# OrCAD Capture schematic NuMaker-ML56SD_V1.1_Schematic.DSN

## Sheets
1 Nu-Link2-Me: size A3; title: Nu-Link2-Me; rev: 1.0; company: CMHuang; note: Nu-Link2-Me
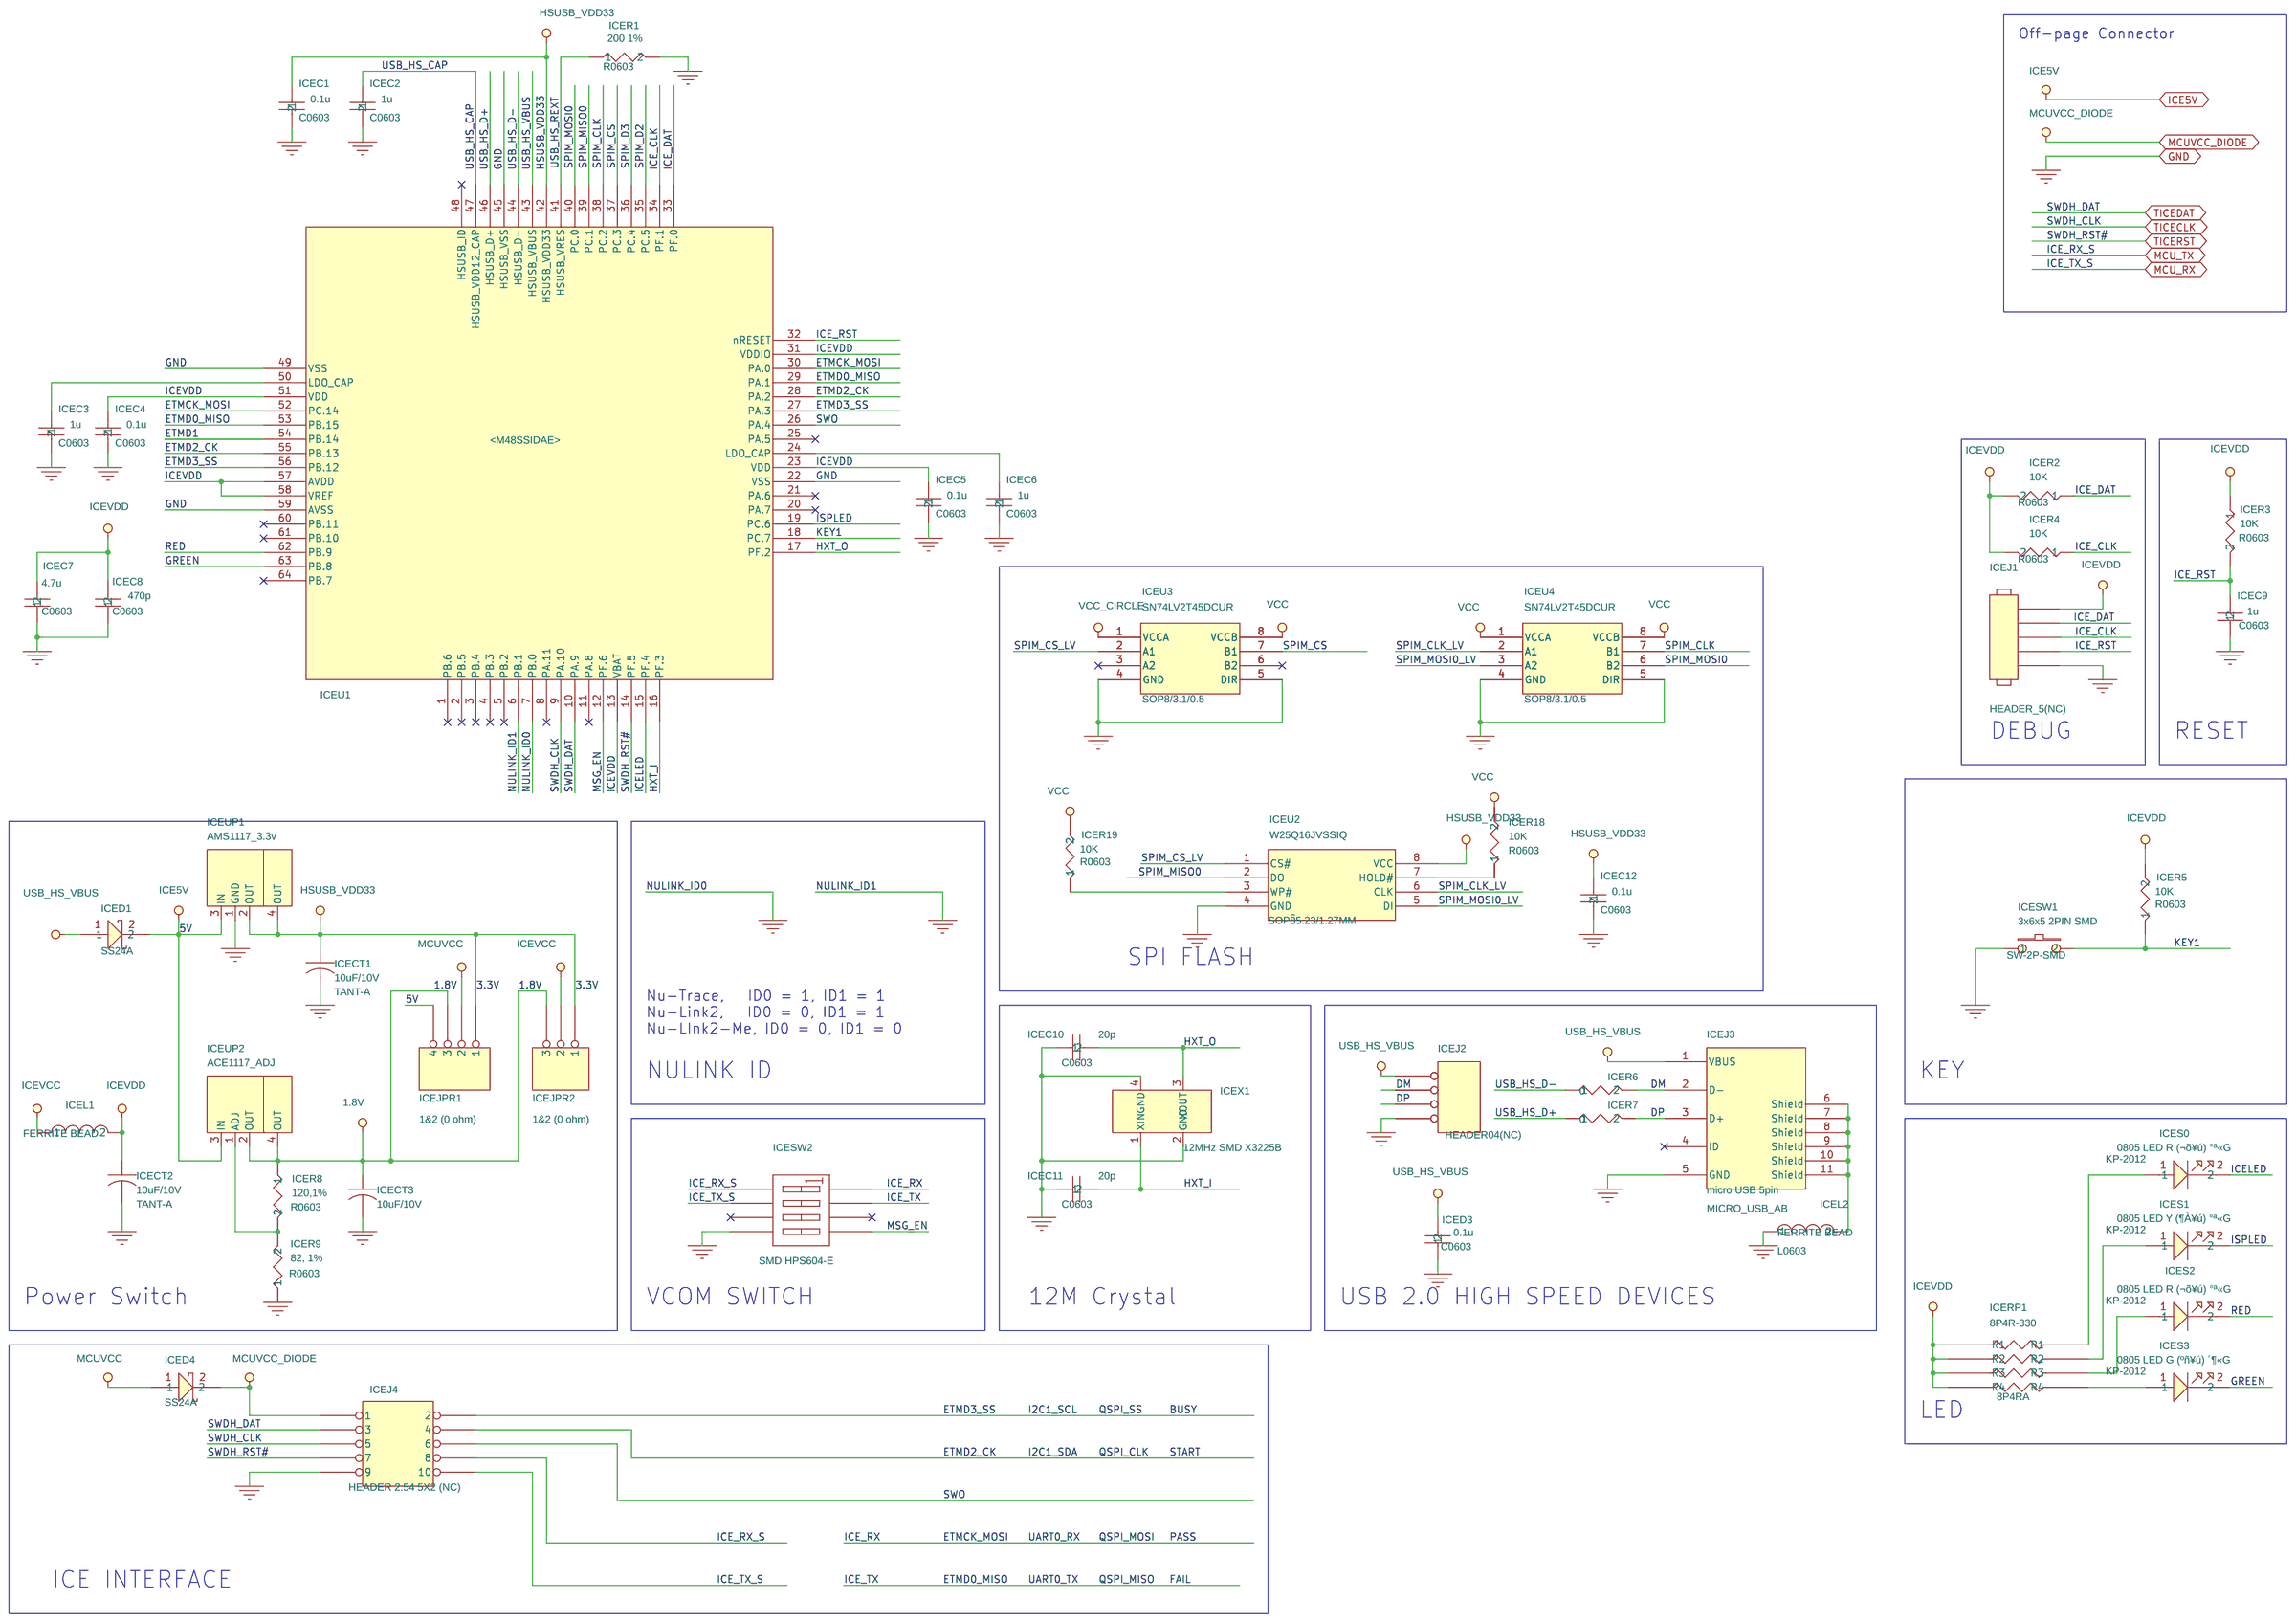
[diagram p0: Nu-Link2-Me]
2 ML56SD1AE: size Custom; title: ML56SD1AE; rev: v1.1; note: NuMaker-ML56SD
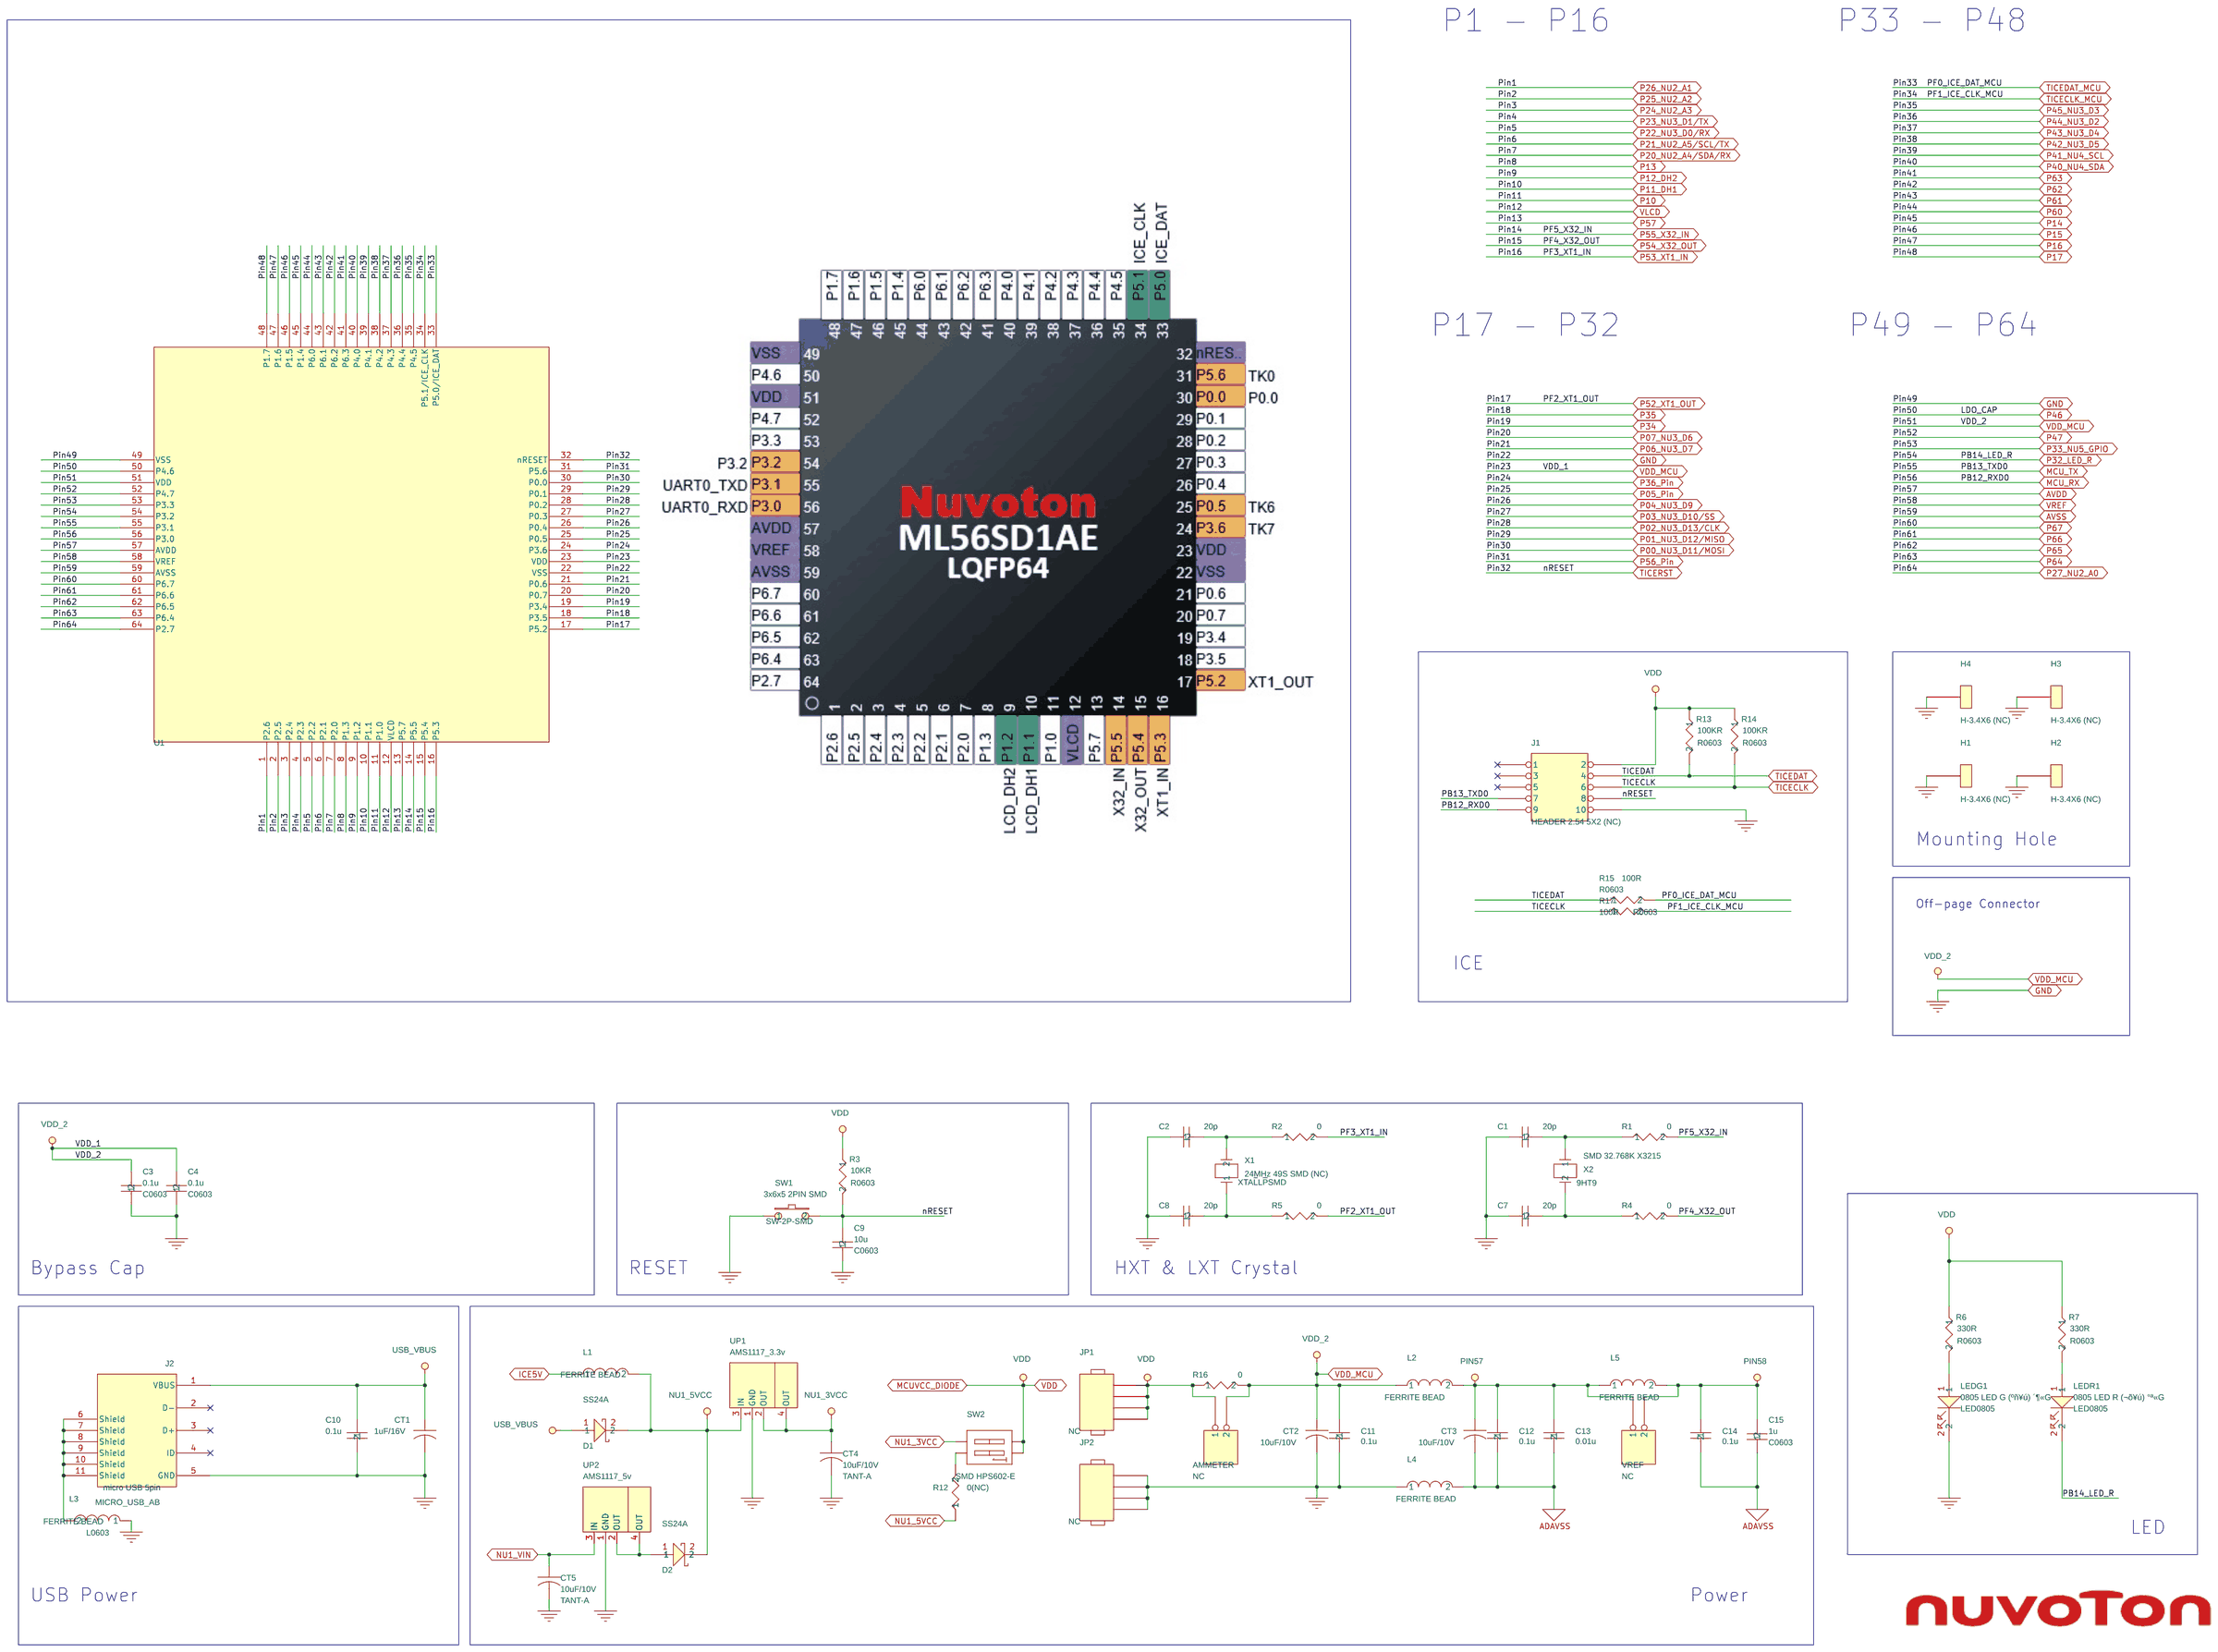
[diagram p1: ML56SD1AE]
3 Ext. Connector: size Custom; title: Ext. Connector; rev: v1.1; note: NuMaker-ML56SD
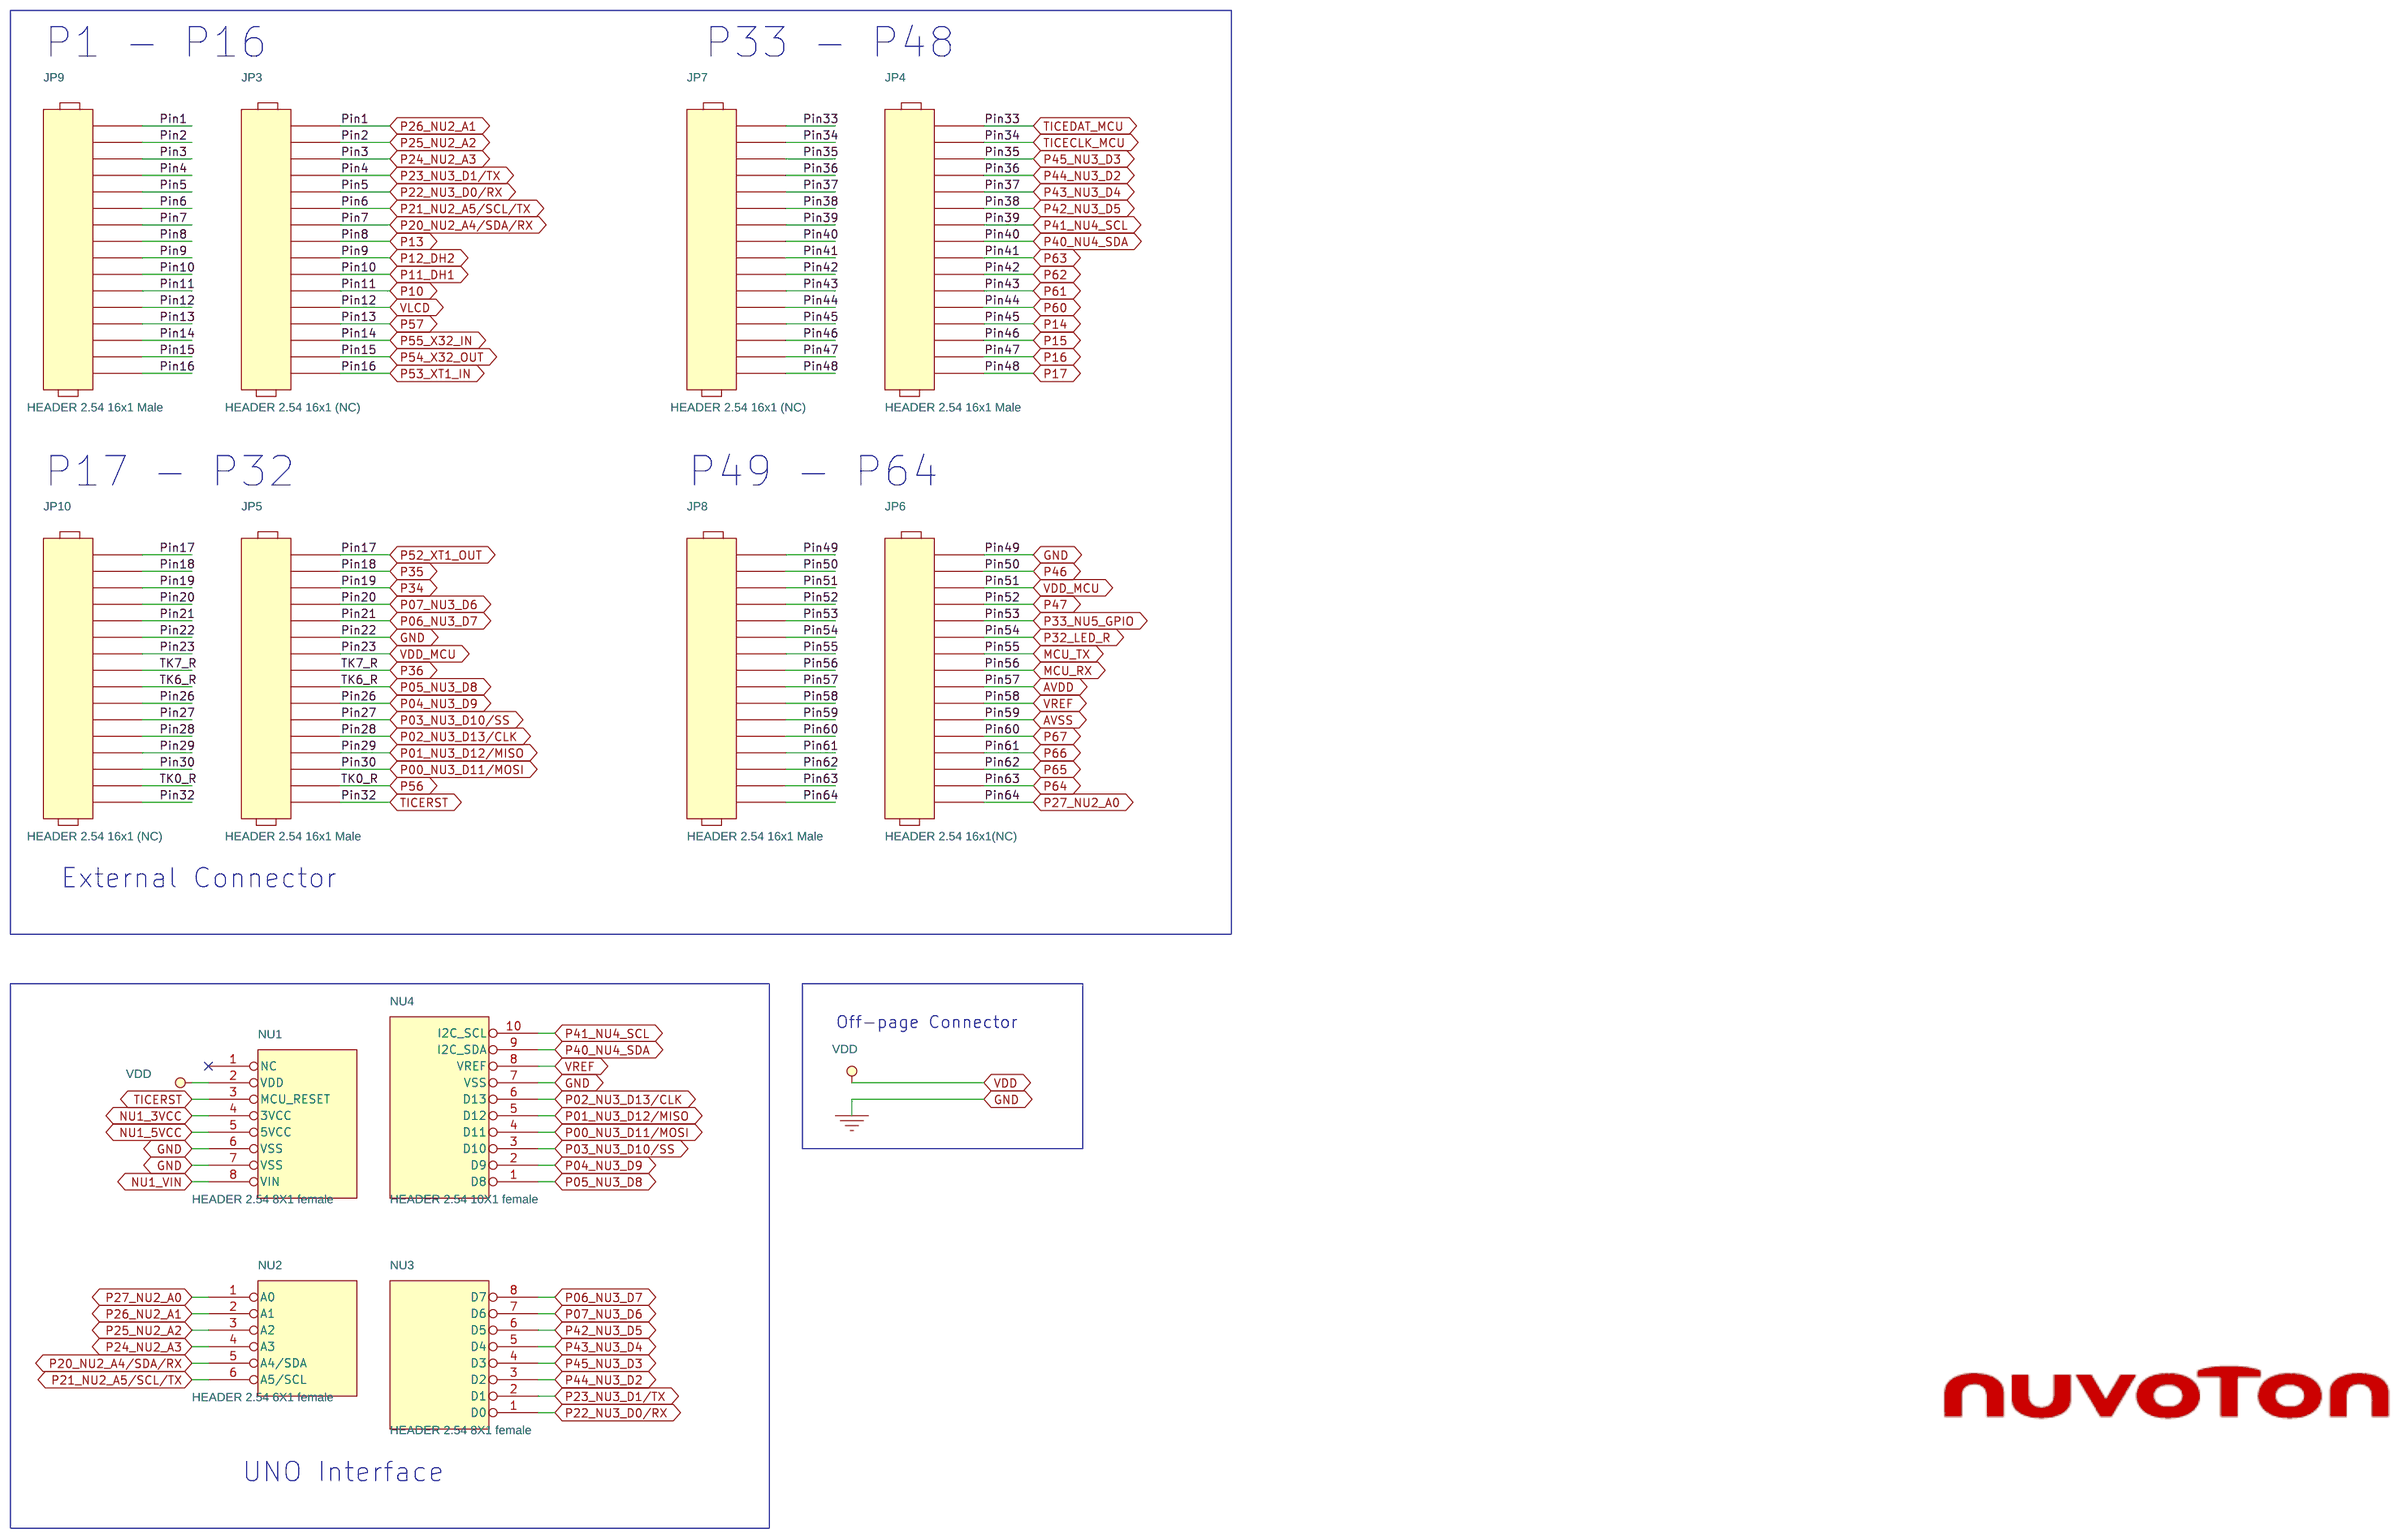
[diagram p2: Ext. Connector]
4 TK & LCD Cap: size A; title: Touch_Key &  LCD Power Cap; rev: v1.1; note: NuMaker-ML56SD
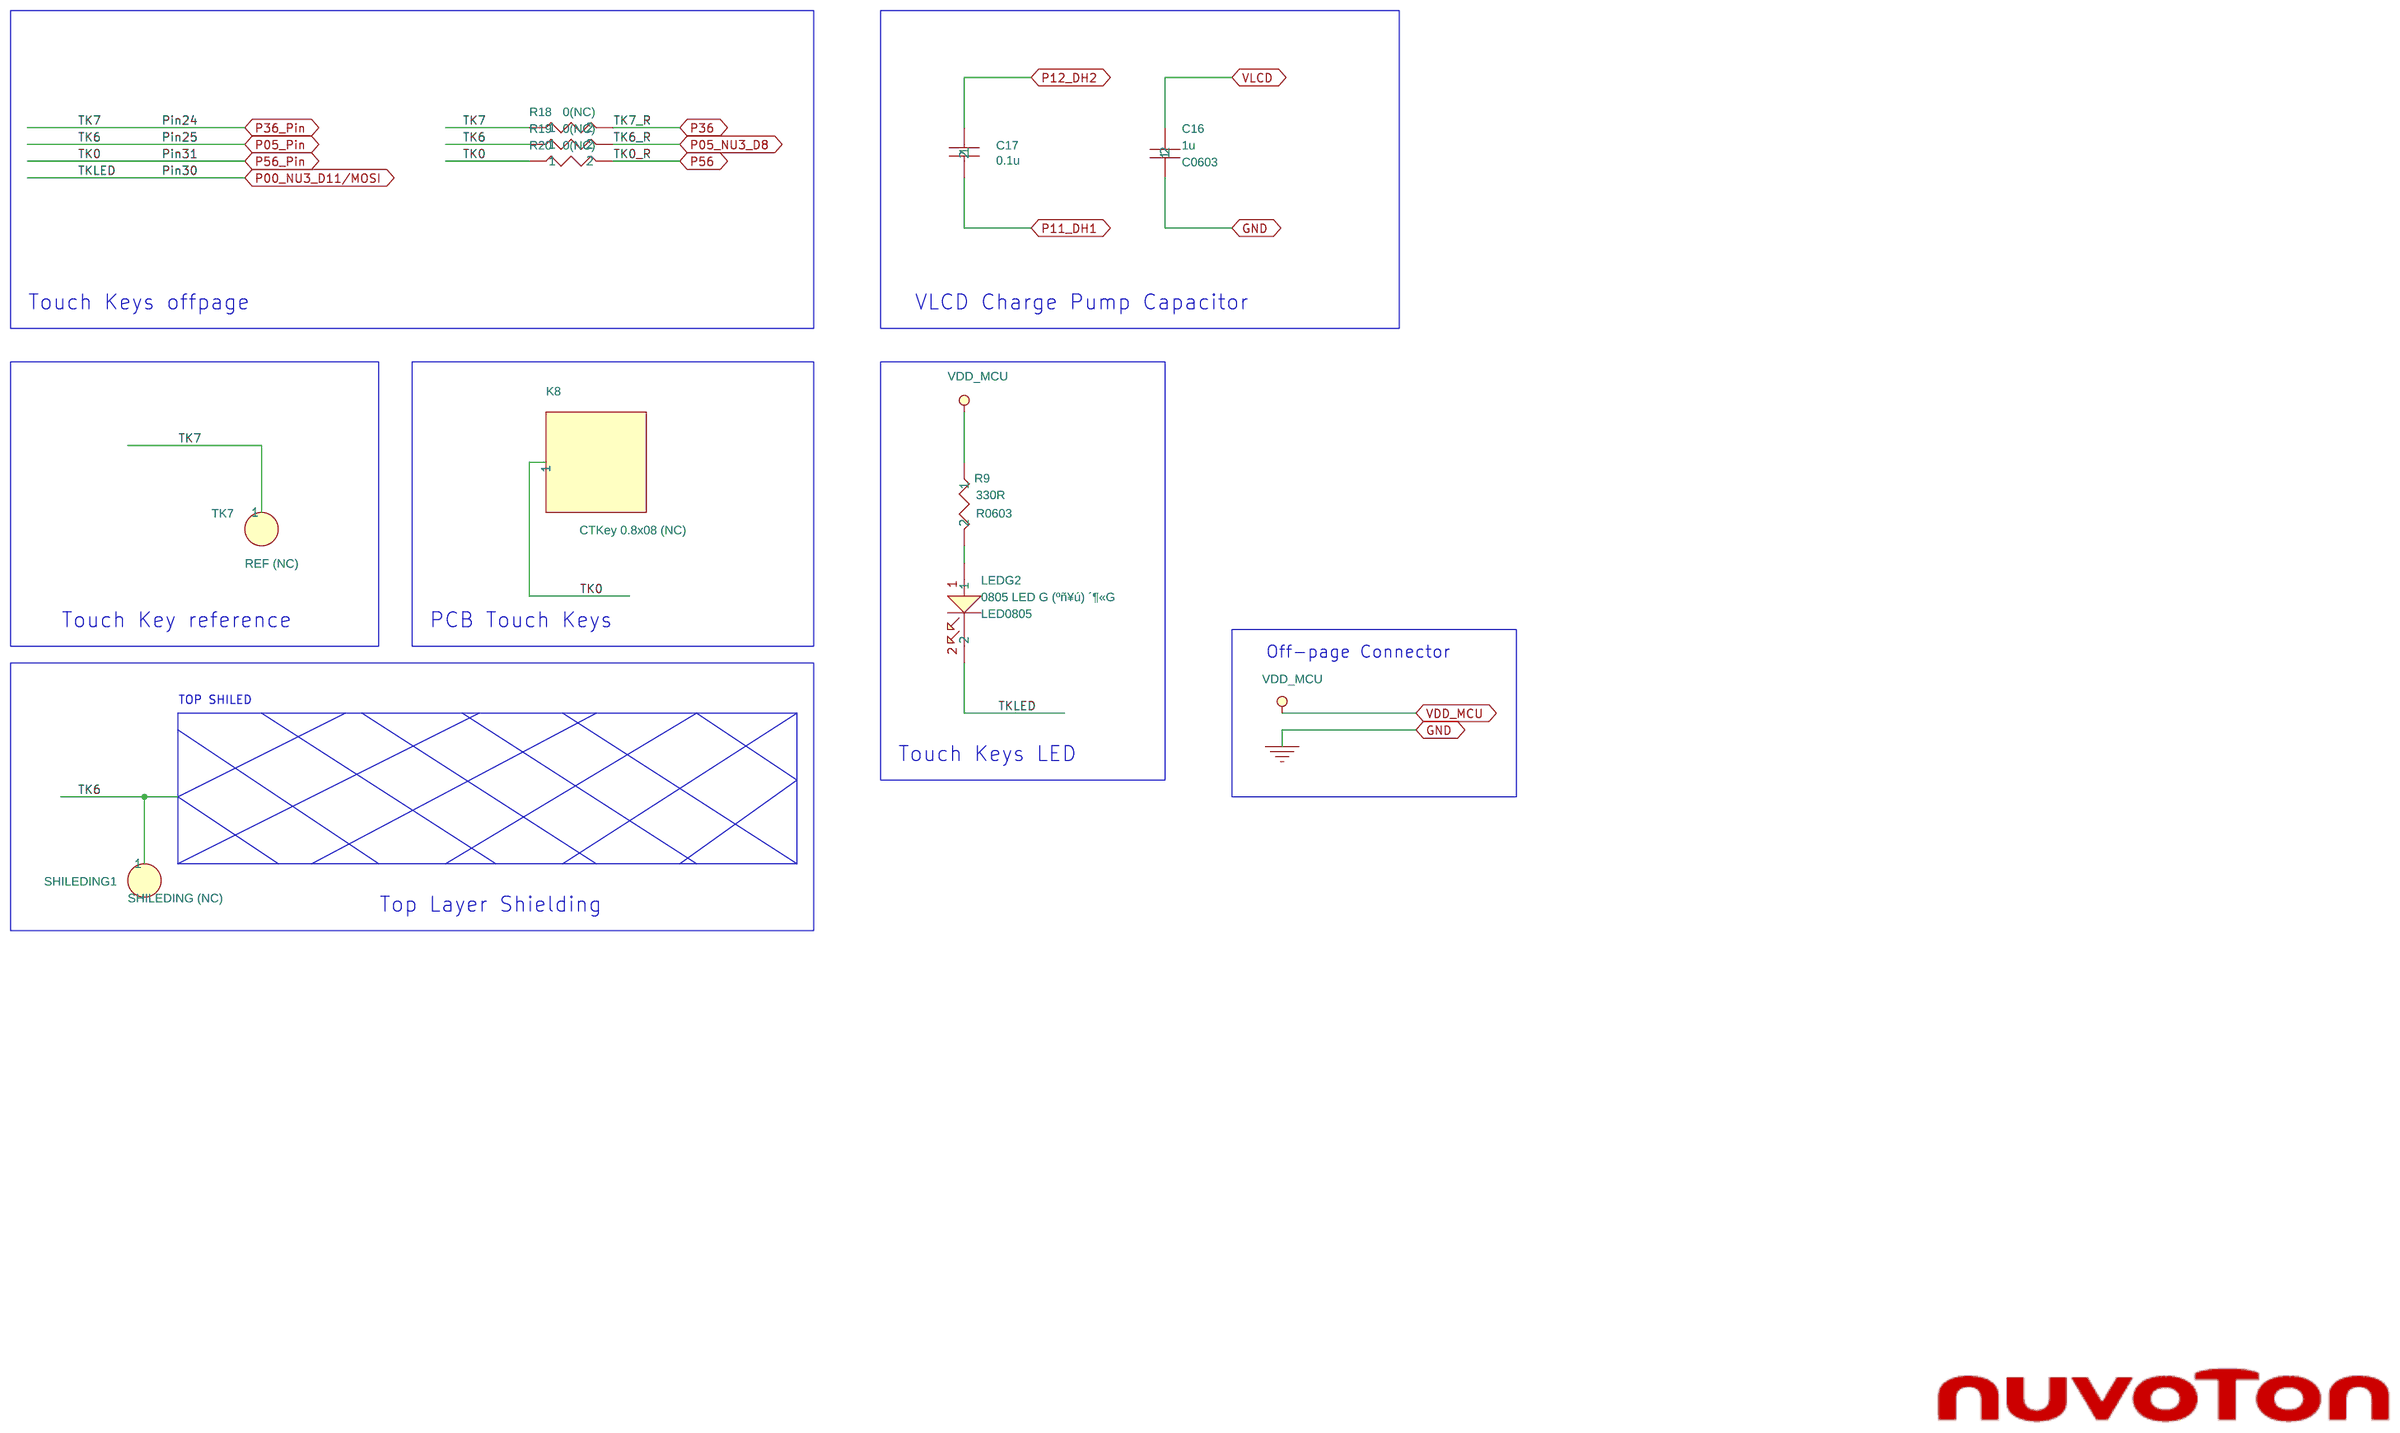
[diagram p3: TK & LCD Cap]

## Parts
sheet Ext. Connector
JP3  HEADER 2.54 16x1 (NC)  [HEADER16X1]
JP4  HEADER 2.54 16x1 Male  [HEADER16X1]
JP5  HEADER 2.54 16x1 Male  [HEADER16X1]
JP6  HEADER 2.54 16x1(NC)  [HEADER16X1]
JP7  HEADER 2.54 16x1 (NC)  [HEADER16X1]
JP8  HEADER 2.54 16x1 Male  [HEADER16X1]
JP9  HEADER 2.54 16x1 Male  [HEADER16X1]
JP10  HEADER 2.54 16x1 (NC)  [HEADER16X1]
NU1  HEADER 2.54 8X1 female  [SIP-8P]
NU2  HEADER 2.54 6X1 female  [SIP-6P]
NU3  HEADER 2.54 8X1 female  [SIP-8P]
NU4  HEADER 2.54 10X1 female  [SIP-10P]
sheet ML56SD1AE
AMMETER  NC  [HEADER2X1]
C1  20p  [C0603]
C2  20p  [C0603]
C3  0.1u  [C0603]
C4  0.1u  [C0603]
C7  20p  [C0603]
C8  20p  [C0603]
C9  10u  [C0603]
C10  0.1u  [C0603]
C11  0.1u  [C0603]
C12  0.1u  [C0603]
C13  0.01u  [C0603]
C14  0.1u  [C0603]
C15  1u  [C0603]
CT1  1uF/16V  [TANT-A]
CT2  10uF/10V  [TANT-A]
CT3  10uF/10V  [TANT-A]
CT4  10uF/10V  [TANT-A]
CT5  10uF/10V  [TANT-A]
D1  SS24A  [RB060L]
D2  SS24A  [RB060L]
H1  H-3.4X6 (NC)  [H-3.4X6]
H2  H-3.4X6 (NC)  [H-3.4X6]
H3  H-3.4X6 (NC)  [H-3.4X6]
H4  H-3.4X6 (NC)  [H-3.4X6]
J1  HEADER 2.54 5X2 (NC)  [HEADER5X2]
J2  micro USB 5pin  [MICRO_USB_AB]
JP1  NC  [header1x4]
JP2  NC  [header1x4]
L1  FERRITE BEAD  [L0603]
L2  FERRITE BEAD  [L0603]
L3  FERRITE BEAD  [L0603]
L4  FERRITE BEAD  [L0603]
L5  FERRITE BEAD  [L0603]
LEDG1  0805 LED G (ºñ¥ú) ´¶«G  [LED0805]
LEDR1  0805 LED R (¬õ¥ú) °ª«G  [LED0805]
R1  0  [R0603]
R2  0  [R0603]
R3  10KR  [R0603]
R4  0  [R0603]
R5  0  [R0603]
R6  330R  [R0603]
R7  330R  [R0603]
R12  0(NC)  [R0603]
R13  100KR  [R0603]
R14  100KR  [R0603]
R15  100R  [R0603]
R16  0  [R0603]
R17  100R  [R0603]
SW1  3x6x5 2PIN SMD  [SW-2P-SMD]
SW2  SMD HPS602-E  [SW1X2]
U1  ML56SD1AE  [MCU_LQFP_64_7X7]
UP1  AMS1117_3.3v  [SOT-223-1]
UP2  AMS1117_5v  [SOT-223-1]
VREF  NC  [HEADER2X1]
X1  24MHz 49S SMD (NC)  [XTAL\LP\SMD]
X2  SMD 32.768K X3215  [9HT9]
sheet Nu-Link2-Me
ICEC1  0.1u  [C0603]
ICEC2  1u  [C0603]
ICEC3  1u  [C0603]
ICEC4  0.1u  [C0603]
ICEC5  0.1u  [C0603]
ICEC6  1u  [C0603]
ICEC7  4.7u  [C0603]
ICEC8  470p  [C0603]
ICEC9  1u  [C0603]
ICEC10  20p  [C0603]
ICEC11  20p  [C0603]
ICEC12  0.1u  [C0603]
ICECT1  10uF/10V  [TANT-A]
ICECT2  10uF/10V  [TANT-A]
ICECT3  10uF/10V  [TANT-A]
ICED1  SS24A  [RB060L]
ICED3  0.1u  [C0603]
ICED4  SS24A  [RB060L]
ICEJ1  HEADER_5(NC)  [HEADER5X1]
ICEJ2  HEADER04(NC)  [HEADER04]
ICEJ3  micro USB 5pin  [MICRO_USB_AB]
ICEJ4  HEADER 2.54 5X2 (NC)  [HEADER5X2]
ICEJPR1  1&2 (0 ohm)  [R0603X3]
ICEJPR2  1&2 (0 ohm)  [R0603X2]
ICEL1  FERRITE BEAD  [L0603]
ICEL2  FERRITE BEAD  [L0603]
ICER1  200 1%  [R0603]
ICER2  10K  [R0603]
ICER3  10K  [R0603]
ICER4  10K  [R0603]
ICER5  10K  [R0603]
ICER6  0  [R0603]
ICER7  0  [R0603]
ICER8  120,1%  [R0603]
ICER9  82, 1%  [R0603]
ICER18  10K  [R0603]
ICER19  10K  [R0603]
ICERP1  8P4R-330  [8P4RA]
ICES0  0805 LED R (¬õ¥ú) °ª«G  [KP-2012]
ICES1  0805 LED Y (¶À¥ú) °ª«G  [KP-2012]
ICES2  0805 LED R (¬õ¥ú) °ª«G  [KP-2012]
ICES3  0805 LED G (ºñ¥ú) ´¶«G  [KP-2012]
ICESW1  3x6x5 2PIN SMD  [SW-2P-SMD]
ICESW2  SMD HPS604-E  [SW1X4]
ICEU1  M48SSIDAE  [LQFP64_7x7_M48SSIDAE]
ICEU2  W25Q16JVSSIQ  [SOP8\5.23/1.27MM]
ICEU3  SN74LV2T45DCUR  [SOP8/3.1/0.5]
ICEU4  SN74LV2T45DCUR  [SOP8/3.1/0.5]
ICEUP1  AMS1117_3.3v  [SOT-223-1]
ICEUP2  ACE1117_ADJ  [SOT-223-1]
ICEX1  12MHz SMD X3225B  [CRYSTAL_SMD]
sheet TK & LCD Cap
C16  1u  [C0603]
C17  0.1u  [C0603]
K8  CTKey 0.8x08 (NC)  [PAD_8mm]
LEDG2  0805 LED G (ºñ¥ú) ´¶«G  [LED0805]
R9  330R  [R0603]
R18  0(NC)  [R0603]
R19  0(NC)  [R0603]
R20  0(NC)  [R0603]
SHILEDING1  SHILEDING (NC)  [PAD1mm]
TK7  REF (NC)  [PAD1mm]

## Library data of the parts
JP3-JP10 = HEADER_16
NU1 = POWER_CONNECT_0
NU2 = ADC_CONNECT_0
NU3 = PWM0_CONNECT_0
NU4 = PWM1_CONNECT_1
AMMETER = HEADER_2
C1 = C_20p_3
C2 = C_20p
C3 = CAP-C_2: Package: 0603; element_no: C0004
C4 ICEC5 = CAP-C: Package: 0603; element_no: C0004
C7 = C_20p_1
C8 = C_20p_2
C9 = CAP-C_3: Package: 0603; element_no: C0006
C10 = C_0.1u_4: element_no: C0004
C11 = C_0.1u_2: element_no: C0004
C12 = C_0.1u_3: element_no: C0004
C13 = C_0.1u: element_no: C0003
C14 = C_0.1u_1: element_no: C0004
C15 = CAP-C_1: Package: 0603; element_no: C0006
CT1 = C_1uF_16V
CT2-CT5 ICECT1-ICECT3 = C_10uF_10V
D1 ICED1 = D_SS24A_1
D2 ICED4 = D_SS24A
H1-H4 = TEST_POINT
ICEJ4 J1 = HEADER_5X2
ICEJ3 J2 = micro_USB_5pin_0
JP1 JP2 = HEADER_4
ICEL1 L1 = FERRITE_BEAD
L2 = FERRITE_BEAD_4
L3 = FERRITE_BEAD_3
ICEL2 L4 = FERRITE_BEAD_1
L5 = FERRITE_BEAD_2
LEDG1 = LED_0_1: Package: KP-2012; Vendor: Kingbright
LEDG2 LEDR1 = LED_0: Package: KP-2012; Vendor: Kingbright
R1 = R_0
R2 = R_0_4
ICER1 R3 = R_0_5: Package: 0603
R4 = R_0_11
R5 R19 = R_0_2
ICER5 R6 = R_0_8: Package: 0603
ICER2 R7 = R_0_1: Package: 0603
R12 = R_0_10
ICER19 R13 = R_0_7: Package: 0603
R14 = R_0_9: Package: 0603
ICER18 R15 = R_0_6: Package: 0603
R16 R18 = R_0_3
R17 = R_0_12: Package: 0603
ICESW1 SW1 = SW_PUSHBUTTON_0
SW2 = SW_DIP-4_2
U1 = ML56SD1AE
ICEUP1 UP1 UP2 = TO-247_Regulator_10
VREF = HEADER_2_1
X1 = Xtal_12MHz
X2 = Xtal_32.768K
ICEC1 = CAP-C_11: Package: 0603; element_no: C0004
ICEC2 = CAP-C_9: Package: 0603; element_no: C0006
ICEC3 = CAP-C_2: Package: 0603; element_no: C0006
ICEC4 = CAP-C_10: Package: 0603; element_no: C0004
ICEC6 = CAP-C_12: Package: 0603; element_no: C0006
ICEC7 = CAP-C_5: Package: 0603
ICEC8 = CAP-C_6: Package: 0603
ICEC9 = CAP-C_7: Package: 0603; element_no: C0006
ICEC10 = CAP-C_3: Package: 0603
ICEC11 = CAP-C_4: Package: 0603
ICEC12 = CAP-C_8: Package: 0603; element_no: C0004
ICED3 = CAP-C_1: Package: 0603; element_no: C0004
ICEJ1 = HEADER_5_v2
ICEJ2 = HEADER_4_v2
ICEJPR1 = HEADER_3_0
ICEJPR2 = HEADER_3
ICER3 = R_0_4: Package: 0603
ICER4 = R_0_3: Package: 0603
ICER6 = R_33
ICER7 = R_33_1
ICER8 R9 = R_0: Package: 0603
ICER9 = R_0_2: Package: 0603
ICERP1 = R-PACK8_0
ICES0 = LED_0_3: Vendor: Kingbright
ICES1 = LED_0_2: Vendor: Kingbright
ICES2 = LED_0_1: Vendor: Kingbright
ICES3 = LED_0: Vendor: Kingbright
ICESW2 = SW_DIP-4_SM
ICEU1 = M487SIDAE_0: M487SIDAE: <M48SSIDAE>
ICEU2 = W25P10_20_40_SOIC_0: Package: SOP8; Vendor: WINBOND
ICEU3 ICEU4 = SN74LV2T45
ICEUP2 = TO-247_Regulator_0
ICEX1 = Crystal_SMD_1
C16 = CAP-C: Package: 0603; element_no: C0006
C17 = C_0.1u: element_no: C0004
K8 = CTKey_5
R20 = R_0_1
SHILEDING1 TK7 = CTKey_7

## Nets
1.8V: ICECT3.1 ICEJPR1.3 ICEJPR2.3 ICER8.1 ICEUP2.2(OUT) ICEUP2.4(OUT)
3.3V: ICEC1.1 ICEC12.1 ICECT1.1 ICEJPR1.1 ICEJPR2.1 ICER18.2 ICER19.2 ICEU1.42(HSUSB_VDD33) ICEU2.8(VCC) ICEU3.1(VCCA) ICEU4.1(VCCA) ICEUP1.2(OUT) ICEUP1.4(OUT)
AVDD: C12.1 C13.1 CT3.1 JP6.9 JP8.9 L2.2 L5.1 U1.57(AVDD) VREF.1
AVSS: C12.2 C13.2 C14.2 C15.1 CT3.2 JP6.11 JP8.11 L4.2 U1.59(AVSS)
GND: C1.1 C2.1 C3.1 C4.1 C7.1 C8.1 C9.1 C10.2 C11.2 C16.1 CT1.2 CT2.2 CT4.2 CT5.2 H1.1 H2.1 H3.1 H4.1 ICEC1.2 ICEC2.2 ICEC3.2 ICEC4.2 ICEC5.2 ICEC6.2 ICEC7.1 ICEC8.1 ICEC9.1 ICEC10.1 ICEC11.1 ICEC12.2 ICECT1.2 ICECT2.2 ICECT3.2 ICED3.1 ICEJ1.5 ICEJ2.4 ICEJ3.5(GND) ICEJ4.9 ICEL2.1 ICER1.2 ICER9.1 ICESW1.1 ICESW2.4(A4) ICEU1.6(PB.1) ICEU1.7(PB.0) ICEU1.22(VSS) ICEU1.45(HSUSB_VSS) ICEU1.49(VSS) ICEU1.59(AVSS) ICEU2.4(GND) ICEU3.4(GND) ICEU3.5(DIR) ICEU4.4(GND) ICEU4.5(DIR) ICEUP1.1(GND) ICEX1.2(GND) ICEX1.4(GND) J1.10 J2.5(GND) JP2.1 JP2.2 JP2.3 JP2.4 JP5.6 JP6.1 JP8.1 JP10.6 L3.1 L4.1 LEDG1.2 NU1.6(VSS) NU1.7(VSS) NU4.7(VSS) SW1.1 U1.22(VSS) U1.49(VSS) UP1.1(GND) UP2.1(GND)
VDD: AMMETER.1 ICED4.2 ICEJ4.1 J1.2 JP1.1 JP1.2 JP1.3 JP1.4 NU1.2(VDD) R3.1 R6.1 R7.1 R13.1 R14.1 R16.1 SW2.3(B1) SW2.4(B2)
VDD_MCU: AMMETER.2 C3.2 C4.2 C11.1 CT2.1 JP5.7 JP6.3 JP8.3 JP10.7 L2.1 R9.1 R16.2 U1.23(VDD) U1.51(VDD)
BUSY: ICEJ4.2 ICEU1.27(PA.3) ICEU1.56(PB.12)
DM: ICEJ2.2 ICEJ3.2(D-) ICER6.2
DP: ICEJ2.3 ICEJ3.3(D+) ICER7.2
ETMD1: ICEU1.54(PB.14)
ETMD2_CK: ICEJ4.4 ICEU1.28(PA.2) ICEU1.55(PB.13)
GREEN: ICES3.2 ICEU1.63(PB.8)
HXT_I: ICEC11.2 ICEU1.16(PF.3) ICEX1.1(XIN)
HXT_O: ICEC10.2 ICEU1.17(PF.2) ICEX1.3(XOUT)
ICE5V: ICED1.2 ICEJPR1.4 ICEUP1.3(IN) ICEUP2.3(IN) L1.1
ICE_CLK: ICEJ1.3 ICER4.1 ICEU1.34(PF.1)
ICE_DAT: ICEJ1.2 ICER2.1 ICEU1.33(PF.0)
ICE_RST: ICEC9.2 ICEJ1.4 ICER3.2 ICEU1.32(nRESET)
ICE_RX: ICESW2.8(B1) ICEU1.30(PA.0) ICEU1.52(PC.14)
ICE_TX: ICESW2.7(B2) ICEU1.29(PA.1) ICEU1.53(PB.15)
ICELED: ICES0.2 ICEU1.15(PF.4)
ICEVCC: ICEJPR2.2 ICEL1.1
ICEVDD: ICEC4.1 ICEC5.1 ICEC7.2 ICEC8.2 ICECT2.1 ICEJ1.1 ICEL1.2 ICER2.2 ICER3.1 ICER4.2 ICER5.2 ICERP1.1(R1) ICERP1.3(R2) ICERP1.5(R3) ICERP1.7(R4) ICEU1.13(VBAT) ICEU1.23(VDD) ICEU1.31(VDDIO) ICEU1.51(VDD) ICEU1.57(AVDD) ICEU1.58(VREF) ICEU3.8(VCCB) ICEU4.8(VCCB)
ISPLED: ICES1.2 ICEU1.19(PC.6)
KEY1: ICER5.1 ICESW1.2 ICEU1.18(PC.7)
MCU_RX: ICEJ4.10 ICESW2.2(A2) J1.9 JP6.8 JP8.8 U1.56(P3.0)
MCU_TX: ICEJ4.8 ICESW2.1(A1) J1.7 JP6.7 JP8.7 U1.55(P3.1)
MCUVCC: ICED4.1 ICEJPR1.2
MSG_EN: ICESW2.5(B4) ICEU1.12(PF.6)
NU1_3VCC: CT4.1 NU1.4(3VCC) SW2.2(A2) UP1.2(OUT) UP1.4(OUT)
NU1_5VCC: D1.2 D2.2 L1.2 NU1.5(5VCC) R12.1 UP1.3(IN)
NU1_VIN: CT5.1 NU1.8(VIN) UP2.3(IN)
P00_NU3_D11/MOSI: JP5.14 JP10.14 LEDG2.2 NU4.4(D11) U1.30(P0.0)
P01_NU3_D12/MISO: JP5.13 JP10.13 NU4.5(D12) U1.29(P0.1)
P02_NU3_D13/CLK: JP5.12 JP10.12 NU4.6(D13) U1.28(P0.2)
P03_NU3_D10/SS: JP5.11 JP10.11 NU4.3(D10) U1.27(P0.3)
P04_NU3_D9: JP5.10 JP10.10 NU4.2(D9) U1.26(P0.4)
P05_NU3_D8: JP5.9 JP10.9 NU4.1(D8) R19.2
P05_Pin: R19.1 SHILEDING1.1 U1.25(P0.5)
P06_NU3_D7: JP5.5 JP10.5 NU3.8(D7) U1.21(P0.6)
P07_NU3_D6: JP5.4 JP10.4 NU3.7(D6) U1.20(P0.7)
P10: JP3.11 JP9.11 U1.11(P1.0)
P11_DH1: C17.2 JP3.10 JP9.10 U1.10(P1.1)
P12_DH2: C17.1 JP3.9 JP9.9 U1.9(P1.2)
P13: JP3.8 JP9.8 U1.8(P1.3)
P14: JP4.13 JP7.13 U1.45(P1.4)
P15: JP4.14 JP7.14 U1.46(P1.5)
P16: JP4.15 JP7.15 U1.47(P1.6)
P17: JP4.16 JP7.16 U1.48(P1.7)
P20_NU2_A4/SDA/RX: JP3.7 JP9.7 NU2.5(A4/SDA) U1.7(P2.0)
P21_NU2_A5/SCL/TX: JP3.6 JP9.6 NU2.6(A5/SCL) U1.6(P2.1)
P22_NU3_D0/RX: JP3.5 JP9.5 NU3.1(D0) U1.5(P2.2)
P23_NU3_D1/TX: JP3.4 JP9.4 NU3.2(D1) U1.4(P2.3)
P24_NU2_A3: JP3.3 JP9.3 NU2.4(A3) U1.3(P2.4)
P25_NU2_A2: JP3.2 JP9.2 NU2.3(A2) U1.2(P2.5)
P26_NU2_A1: JP3.1 JP9.1 NU2.2(A1) U1.1(P2.6)
P27_NU2_A0: JP6.16 JP8.16 NU2.1(A0) U1.64(P2.7)
P32_LED_R: JP6.6 JP8.6 LEDR1.2 U1.54(P3.2)
P33_NU5_GPIO: JP6.5 JP8.5 U1.53(P3.3)
P34: JP5.3 JP10.3 U1.19(P3.4)
P35: JP5.2 JP10.2 U1.18(P3.5)
P36: JP5.8 JP10.8 R18.2
P36_Pin: R18.1 TK7.1 U1.24(P3.6)
P40_NU4_SDA: JP4.8 JP7.8 NU4.9(I2C_SDA) U1.40(P4.0)
P41_NU4_SCL: JP4.7 JP7.7 NU4.10(I2C_SCL) U1.39(P4.1)
P42_NU3_D5: JP4.6 JP7.6 NU3.6(D5) U1.38(P4.2)
P43_NU3_D4: JP4.5 JP7.5 NU3.5(D4) U1.37(P4.3)
P44_NU3_D2: JP4.4 JP7.4 NU3.3(D2) U1.36(P4.4)
P45_NU3_D3: JP4.3 JP7.3 NU3.4(D3) U1.35(P4.5)
P46: JP6.2 JP8.2 U1.50(P4.6)
P47: JP6.4 JP8.4 U1.52(P4.7)
P52_XT1_OUT: JP5.1 JP10.1 R5.2 U1.17(P5.2)
P53_XT1_IN: JP3.16 JP9.16 R2.2 U1.16(P5.3)
P54_X32_OUT: JP3.15 JP9.15 R4.2 U1.15(P5.4)
P55_X32_IN: JP3.14 JP9.14 R1.2 U1.14(P5.5)
P56: JP5.15 JP10.15 R20.2
P56_Pin: K8.1 R20.1 U1.31(P5.6)
P57: JP3.13 JP9.13 U1.13(P5.7)
P60: JP4.12 JP7.12 U1.44(P6.0)
P61: JP4.11 JP7.11 U1.43(P6.1)
P62: JP4.10 JP7.10 U1.42(P6.2)
P63: JP4.9 JP7.9 U1.41(P6.3)
P64: JP6.15 JP8.15 U1.63(P6.4)
P65: JP6.14 JP8.14 U1.62(P6.5)
P66: JP6.13 JP8.13 U1.61(P6.6)
P67: JP6.12 JP8.12 U1.60(P6.7)
RED: ICES2.2 ICEU1.62(PB.9)
SPIM_CLK: ICEU1.38(PC.2) ICEU4.7(B1)
SPIM_CLK_LV: ICEU2.6(CLK) ICEU4.2(A1)
SPIM_CS: ICEU1.37(PC.3) ICEU3.7(B1)
SPIM_CS_LV: ICEU2.1(CS#) ICEU3.2(A1)
SPIM_D2: ICEU1.35(PC.5)
SPIM_D3: ICEU1.36(PC.4)
SPIM_MISO0: ICEU1.39(PC.1) ICEU2.2(DO)
SPIM_MOSI0: ICEU1.40(PC.0) ICEU4.6(B2)
SPIM_MOSI0_LV: ICEU2.5(DI) ICEU4.3(A2)
SWO: ICEJ4.6 ICEU1.26(PA.4)
TICECLK: ICEJ4.5 ICEU1.9(PA.10) J1.6 R14.2 R17.1
TICECLK_MCU: JP4.2 JP7.2 R17.2 U1.34(P5.1/ICE_CLK)
TICEDAT: ICEJ4.3 ICEU1.10(PA.9) J1.4 R13.2 R15.1
TICEDAT_MCU: JP4.1 JP7.1 R15.2 U1.33(P5.0/ICE_DAT)
TICERST: C9.2 ICEJ4.7 ICEU1.14(PF.5) J1.8 JP5.16 JP10.16 NU1.3(MCU_RESET) R3.2 SW1.2 U1.32(nRESET)
USB_HS_CAP: ICEC2.1 ICEU1.47(HSUSB_VDD12_CAP)
USB_HS_D+: ICER7.1 ICEU1.46(HSUSB_D+)
USB_HS_D-: ICER6.1 ICEU1.44(HSUSB_D-)
USB_HS_REXT: ICER1.1 ICEU1.41(HSUSB_VRES)
USB_HS_VBUS: ICED1.1 ICED3.2 ICEJ2.1 ICEJ3.1(VBUS) ICEU1.43(HSUSB_VBUS)
USB_VBUS: C10.1 CT1.1 D1.1 J2.1(VBUS)
VLCD: C16.2 JP3.12 JP9.12 U1.12(VLCD)
VREF: C14.1 C15.2 JP6.10 JP8.10 L5.2 NU4.8(VREF) U1.58(VREF) VREF.2
N16825237: LEDG1.1 R6.2
N16825240: LEDR1.1 R7.2
N16840819: ICEC6.1 ICEU1.24(LDO_CAP)
N16840960: ICEC3.1 ICEU1.50(LDO_CAP)
N17019924: ICER8.2 ICER9.2 ICEUP2.1(ADJ)
N17029977: ICERP1.8(R4) ICES3.1
N17029979: ICERP1.6(R3) ICES2.1
N17030004: ICERP1.4(R2) ICES1.1
N17030010: ICERP1.2(R1) ICES0.1
N17042369: ICEJ3.6(Shield) ICEJ3.7(Shield) ICEJ3.8(Shield) ICEJ3.9(Shield) ICEJ3.10(Shield) ICEJ3.11(Shield) ICEL2.2
N17155328: ICER18.1 ICEU2.7(HOLD#)
N17155343: ICER19.1 ICEU2.3(WP#)
N17159369: C8.2 R5.1 X1.1
N17159371: C2.2 R2.1 X1.2
N17159463: C1.2 R1.1 X2.1
N17159465: C7.2 R4.1 X2.2
N17239175: R12.2 SW2.1(A1)
N17239225: D2.1 UP2.2(OUT) UP2.4(OUT)
N17239660: J2.6(Shield) J2.7(Shield) J2.8(Shield) J2.9(Shield) J2.10(Shield) J2.11(Shield) L3.2
N17243307: LEDG2.1 R9.2

Not connected (* = marked no-connect by the designer): ICEJ3 4(ID)*; ICESW2 3(A3)* 6(B3)*; ICEU1 1(PB.6)* 2(PB.5)* 3(PB.4)* 4(PB.3)* 5(PB.2)* 8(PA.11)* 11(PA.8)* 20(PA.7)* 21(PA.6)* 25(PA.5)* 48(HSUSB_ID)* 60(PB.11)* 61(PB.10)* 64(PB.7)*; ICEU3 3(A2)* 6(B2)*; J1 1* 3* 5*; J2 2(D-)* 3(D+)* 4(ID)*; NU1 1(NC)*

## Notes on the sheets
sheet 1
- Off-page Connector
- DEBUG
- RESET
- SPI FLASH
- Nu-Trace,   ID0 = 1, ID1 = 1
  Nu-Link2,   ID0 = 0, ID1 = 1
  Nu-LInk2-Me, ID0 = 0, ID1 = 0
- NULINK ID
- KEY
- Power Switch
- VCOM SWITCH
- 12M Crystal
- USB 2.0 HIGH SPEED DEVICES
- LED
- ICE INTERFACE
sheet 2
- P1 - P16
- P33 - P48
- P17 - P32
- P49 - P64
- Mounting Hole
- Off-page Connector
- ICE
- Bypass Cap
- RESET
- HXT & LXT Crystal
- LED
- USB Power
- Power
sheet 3
- P1 - P16
- P33 - P48
- P17 - P32
- P49 - P64
- External Connector
- Off-page Connector
- UNO Interface
sheet 4
- Touch Keys offpage
- VLCD Charge Pump Capacitor
- Touch Key reference
- PCB Touch Keys
- Off-page Connector
- TOP SHILED
- Touch Keys LED
- Top Layer Shielding
